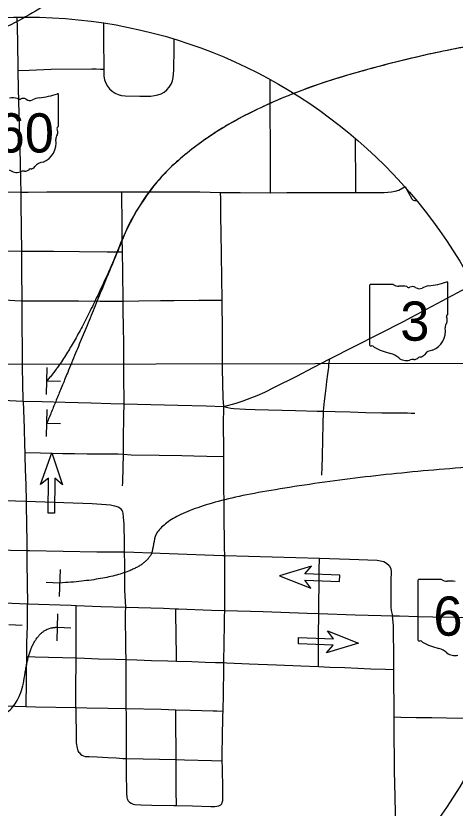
# Model space of a CAD drawing. Extents: x -15.3 to 34, y 0 to 22.
# Drawn here: x 9.062 to 11.664, y 14.569 to 19.257 of the extents above; entities that cross this region are included whole.
import ezdxf

# ---------------------------------------------------------------- set-up
doc = ezdxf.new("R2010")
doc.units = 0
for name, color, linetype in [('GM_X_City_Street', 7, 'Continuous'), ('GM_X_State_Route', 7, 'Continuous'), ('GM_X_State_Shield', 7, 'Continuous'), ('GM_X_Township', 7, 'Continuous'), ('PM_P_Cells', 7, 'Continuous'), ('SH_Text', 7, 'Continuous'), ('SN_P_Signs', 7, 'Continuous')]:
    doc.layers.add(name, color=color, linetype=linetype)

msp = doc.modelspace()

# ---------------------------------------------------------------- linework, layer by layer
at = {"layer": 'GM_X_City_Street'}
for points in [[(9.5818, 19.215), (9.5815, 19.1232), (9.5821, 18.9424)], [(9.0756, 18.9338), (9.1398, 18.9361), (9.2709, 18.9409), (9.5111, 18.9434), (9.5372, 18.943), (9.563, 18.9427), (9.5821, 18.9424), (9.5827, 18.9), (9.5872, 18.8789), (9.5941, 18.8594), (9.6038, 18.841), (9.6164, 18.8246), (9.6317, 18.8106), (9.649, 18.7994), (9.668, 18.7912), (9.6882, 18.7862), (9.7092, 18.7836), (9.7961, 18.7816), (9.8611, 18.7827), (9.8822, 18.7852), (9.9029, 18.7893), (9.9224, 18.7963), (9.9403, 18.8066), (9.9565, 18.8201), (9.9704, 18.836), (9.9815, 18.8538), (9.9888, 18.8729), (9.9935, 18.8933), (9.9971, 18.9361), (9.999, 19.0669), (9.9995, 19.1197)], [(10.5706, 18.2105), (10.5704, 18.2597), (10.5701, 18.3374), (10.5695, 18.4652), (10.5683, 18.713), (10.5675, 18.8804)], [(11.0759, 18.2114), (11.0756, 18.248), (11.073, 18.5315)], [(11.0759, 18.2114), (11.1114, 18.2113), (11.243, 18.2119), (11.2869, 18.2151), (11.3089, 18.219), (11.3306, 18.2258), (11.3682, 18.2468)], [(11.3682, 18.2468), (11.3858, 18.214), (11.4067, 18.1751), (11.4151, 18.1669), (11.4236, 18.1637), (11.434, 18.1639), (11.435, 18.1642)], [(8.6858, 18.2157), (8.8324, 18.2164), (9.0062, 18.2151), (9.0924, 18.2147)], [(9.0924, 18.2147), (9.1346, 18.2145), (9.2462, 18.2154), (9.3541, 18.2165), (9.5199, 18.2152), (9.6887, 18.2155)], [(9.6887, 18.2155), (9.6938, 18.2155), (9.8029, 18.2155), (9.8901, 18.2156), (10.151, 18.2154), (10.2745, 18.2125)], [(9.6934, 17.8601), (9.6923, 17.9454), (9.6908, 18.0561), (9.6892, 18.1749), (9.6887, 18.2155)], [(10.2745, 18.2125), (10.2817, 18.2123), (10.3908, 18.2121), (10.5706, 18.2105)], [(10.2828, 17.5755), (10.2779, 17.9781), (10.2766, 18.0654), (10.2752, 18.1522), (10.2749, 18.1738), (10.2745, 18.2125)], [(10.5706, 18.2105), (10.6674, 18.2111), (10.8493, 18.212), (11.0759, 18.2114)], [(8.6834, 17.8697), (8.714, 17.8694), (8.8594, 17.868), (8.9809, 17.8668), (9.0968, 17.8657)], [(9.0968, 17.8657), (9.2059, 17.8647), (9.2846, 17.864), (9.4379, 17.8625), (9.6024, 17.8609), (9.6529, 17.8604), (9.6934, 17.8601)], [(9.6973, 17.5698), (9.695, 17.7419), (9.6934, 17.8601)], [(8.6815, 17.5982), (8.7641, 17.5927), (9.055, 17.5722), (9.098, 17.5703), (9.0993, 17.5703)], [(9.0993, 17.5703), (9.2765, 17.57), (9.4328, 17.5699), (9.5609, 17.5697), (9.6647, 17.5696), (9.6973, 17.5698)], [(9.6973, 17.5698), (9.791, 17.571), (9.9191, 17.5726), (9.9996, 17.5736), (10.1455, 17.5754), (10.2331, 17.5754), (10.2828, 17.5755)], [(9.7023, 16.9617), (9.702, 17.1313), (9.7019, 17.1759), (9.7018, 17.2205), (9.7017, 17.325), (9.6994, 17.4116), (9.6979, 17.5193), (9.6973, 17.5698)], [(10.2928, 16.9462), (10.2889, 16.9942), (10.2866, 17.1702), (10.2863, 17.1911), (10.2852, 17.3878), (10.2828, 17.5755)], [(10.8832, 16.9175), (10.8903, 16.9762), (10.8958, 17.0217), (10.8997, 17.0542), (10.9045, 17.0936), (10.9098, 17.1378), (10.9131, 17.1654), (10.9146, 17.1773), (10.9163, 17.1915), (10.9206, 17.2273)], [(8.6759, 16.993), (8.8134, 16.9888), (8.9053, 16.9858), (8.9824, 16.9832), (9.1055, 16.9773)], [(9.6985, 16.6629), (9.6989, 16.6833), (9.7, 16.7539), (9.7022, 16.8874), (9.7023, 16.9617)], [(10.2933, 16.6491), (10.2928, 16.6945), (10.2915, 16.8385), (10.2928, 16.9462)], [(10.2928, 16.9462), (10.3163, 16.9401), (10.3355, 16.9361), (10.3521, 16.9338), (10.4212, 16.9291), (10.4787, 16.9283), (10.718, 16.922), (10.8473, 16.9186), (10.8832, 16.9175)], [(10.8745, 16.539), (10.8756, 16.5869), (10.877, 16.6485), (10.8795, 16.7549), (10.8814, 16.838), (10.8832, 16.9175)], [(10.8832, 16.9175), (10.952, 16.9155), (11.042, 16.9131), (11.1353, 16.9106), (11.2296, 16.908), (11.2729, 16.9082), (11.3815, 16.9076), (11.4033, 16.9068), (11.4249, 16.9053)], [(9.115, 16.6734), (9.2087, 16.6714), (9.339, 16.667), (9.4098, 16.6674), (9.4846, 16.6663), (9.5194, 16.6657), (9.576, 16.6662), (9.6673, 16.6646), (9.6985, 16.6629)], [(9.6939, 16.4767), (9.6958, 16.4951), (9.6973, 16.5879), (9.6984, 16.6576), (9.6985, 16.6623), (9.6985, 16.6629)], [(9.6985, 16.6629), (9.7452, 16.6605), (9.9106, 16.6569), (10.0455, 16.6546), (10.115, 16.6531), (10.1919, 16.6514), (10.2933, 16.6491)], [(10.2988, 16.0642), (10.2983, 16.1114), (10.2964, 16.3175), (10.2944, 16.5238), (10.2933, 16.6491)], [(8.6552, 16.402), (9.0599, 16.3877), (9.1238, 16.3853)], [(9.1238, 16.3853), (9.178, 16.3827), (9.2342, 16.3808), (9.514, 16.371), (9.5958, 16.3661), (9.6223, 16.3627), (9.6455, 16.3586), (9.6678, 16.3511), (9.6844, 16.3412)], [(9.7057, 16.0847), (9.7047, 16.1377), (9.7026, 16.2494), (9.6995, 16.2898), (9.6976, 16.3147), (9.6955, 16.3218), (9.6918, 16.3304), (9.6844, 16.3412)], [(8.6445, 16.1027), (9.1269, 16.0939)], [(9.1269, 16.0939), (9.1417, 16.0937), (9.5422, 16.0864), (9.7057, 16.0847)], [(9.7123, 15.7583), (9.7081, 15.8586), (9.7072, 16.0106), (9.7057, 16.0847)], [(9.7057, 16.0847), (9.7598, 16.0841), (9.9706, 16.0748), (10.2885, 16.0645), (10.2988, 16.0642)], [(10.2989, 15.7382), (10.3001, 15.9242), (10.2988, 16.0642)], [(10.2988, 16.0642), (10.8604, 16.0475)], [(10.8556, 15.7208), (10.8561, 15.804), (10.8572, 15.8692), (10.8591, 15.9787), (10.8604, 16.0475)], [(10.8604, 16.0475), (11.0386, 16.0422), (11.2023, 16.0353), (11.2208, 16.033), (11.2416, 16.0283), (11.2578, 16.0191), (11.2726, 16.0053), (11.2823, 15.9864), (11.2848, 15.9648), (11.2831, 15.9208), (11.2828, 15.7584), (11.2849, 15.7381), (11.2917, 15.7076)], [(9.126, 15.4665), (9.1271, 15.5467), (9.13, 15.6455), (9.1313, 15.7782)], [(9.4194, 15.4573), (9.4194, 15.4606), (9.4196, 15.611), (9.4198, 15.735), (9.4199, 15.7682)], [(9.7143, 15.448), (9.7135, 15.5105), (9.7127, 15.5751), (9.7116, 15.662), (9.7121, 15.7274), (9.7123, 15.7583)], [(10.0128, 15.4386), (10.0124, 15.4691), (10.0091, 15.7223), (10.0087, 15.7481)], [(10.2942, 15.4297), (10.2943, 15.4572), (10.2949, 15.523), (10.2975, 15.6769), (10.298, 15.6988), (10.2989, 15.7382)], [(10.8539, 15.4067), (10.8542, 15.46), (10.8543, 15.4897), (10.8546, 15.5407), (10.855, 15.6093), (10.8555, 15.6986), (10.8556, 15.7208)], [(11.3004, 15.3894), (11.3002, 15.4258), (11.2997, 15.5119), (11.2991, 15.5789), (11.2984, 15.65), (11.2917, 15.7076)], [(9.1233, 15.1698), (9.1237, 15.2126), (9.1243, 15.2805), (9.1251, 15.3682), (9.1259, 15.4594), (9.126, 15.4665)], [(9.126, 15.4665), (9.1759, 15.4649), (9.2543, 15.4625), (9.3388, 15.4598), (9.4194, 15.4573)], [(9.418, 15.1641), (9.4179, 15.2638), (9.4194, 15.4573)], [(9.4194, 15.4573), (9.4681, 15.4557), (9.5506, 15.4532), (9.6515, 15.45), (9.7143, 15.448)], [(9.7159, 15.1581), (9.7157, 15.1713), (9.7156, 15.201), (9.7154, 15.254), (9.715, 15.3698), (9.7143, 15.4453), (9.7143, 15.448)], [(9.7143, 15.448), (9.7792, 15.4459), (9.8651, 15.4432), (9.961, 15.4402), (10.0128, 15.4386)], [(10.0128, 15.4386), (10.1035, 15.4357), (10.1828, 15.4332), (10.244, 15.4313), (10.2942, 15.4297)], [(10.2891, 15.1434), (10.2912, 15.2457), (10.2941, 15.3918), (10.2942, 15.4297)], [(10.2942, 15.4297), (10.3122, 15.4292), (10.4435, 15.4234), (10.6056, 15.4168), (10.7498, 15.411), (10.8539, 15.4067)], [(10.8539, 15.4067), (10.9207, 15.404), (11.0101, 15.4004), (11.1632, 15.3939), (11.2508, 15.391), (11.3004, 15.3894)], [(11.3025, 15.1084), (11.3028, 15.1562), (11.3014, 15.2002), (11.3009, 15.2887), (11.3004, 15.3894)], [(8.6087, 15.1879), (8.7321, 15.1836), (8.9236, 15.1768), (9.1233, 15.1698)], [(9.1233, 15.1698), (9.1783, 15.1689), (9.418, 15.1641)], [(9.418, 15.1641), (9.4828, 15.1628), (9.6087, 15.1603), (9.7159, 15.1581)], [(9.4367, 14.8982), (9.431, 14.9088), (9.4265, 14.923), (9.4219, 14.956), (9.4203, 14.9796), (9.4181, 15.1545), (9.418, 15.1641)], [(9.7173, 14.8622), (9.7174, 14.8681), (9.7178, 14.8897), (9.7165, 14.9768), (9.7168, 14.9983), (9.7168, 15.0203), (9.7165, 15.1057), (9.7163, 15.1275), (9.7159, 15.1581)], [(9.7159, 15.1581), (9.923, 15.1539), (10.0098, 15.1511)], [(10.0108, 14.8564), (10.011, 14.8986), (10.0106, 14.943), (10.0097, 15.0289), (10.009, 15.0984), (10.0094, 15.1205), (10.0098, 15.1511)], [(10.0098, 15.1511), (10.0934, 15.1484), (10.1638, 15.1462), (10.2296, 15.1446), (10.2516, 15.1442), (10.2891, 15.1434)], [(10.2842, 14.8487), (10.2843, 14.902), (10.2859, 14.9808), (10.2886, 15.1166), (10.2891, 15.1434)], [(11.3719, 14.2621), (11.3573, 14.2741), (11.3446, 14.2901), (11.3336, 14.3081), (11.3257, 14.3273), (11.3196, 14.3479), (11.3149, 14.3685), (11.3123, 14.3898), (11.3099, 14.4332), (11.3097, 14.5427), (11.3073, 14.7179), (11.3053, 14.7837), (11.3042, 14.8711), (11.3017, 14.9808), (11.3025, 15.1084)], [(11.3025, 15.1084), (11.3427, 15.1077), (11.4322, 15.106), (11.5263, 15.1042), (11.6114, 15.1025), (11.7164, 15.1005), (11.8596, 15.0978), (11.8946, 15.0971)], [(9.4367, 14.8982), (9.4441, 14.8888), (9.453, 14.8817), (9.4622, 14.8778), (9.4726, 14.8752), (9.4963, 14.8739), (9.5425, 14.8715), (9.6069, 14.8682), (9.6565, 14.8656), (9.6946, 14.8634), (9.7173, 14.8622)], [(9.7343, 14.6047), (9.7276, 14.612), (9.7221, 14.6234), (9.7203, 14.6314), (9.7197, 14.6567), (9.7175, 14.7841), (9.7169, 14.8058), (9.7175, 14.8247), (9.7172, 14.8463), (9.7173, 14.8622)], [(9.7173, 14.8622), (10.0108, 14.8564)], [(10.0108, 14.8564), (10.0603, 14.855), (10.2215, 14.8505), (10.2842, 14.8487)], [(10.0124, 14.5846), (10.0123, 14.6036), (10.0119, 14.6532), (10.0116, 14.7095), (10.0111, 14.7823), (10.0108, 14.8332), (10.0108, 14.8564)], [(10.2754, 14.5882), (10.2813, 14.5952), (10.2846, 14.6019), (10.2874, 14.6132), (10.2883, 14.6237), (10.2882, 14.6826), (10.2852, 14.8052), (10.2842, 14.8487)], [(9.7343, 14.6047), (9.7444, 14.5973), (9.7557, 14.592), (9.767, 14.59), (9.8022, 14.5881), (9.8674, 14.5858), (9.9982, 14.5849), (10.0124, 14.5846)], [(10.0124, 14.5846), (10.1071, 14.5825), (10.216, 14.5782), (10.2409, 14.5789), (10.2517, 14.5797), (10.2636, 14.5821), (10.2754, 14.5882)]]:
    msp.add_lwpolyline(points, dxfattribs=at)
at = {"layer": 'GM_X_State_Route'}
for points in [[(9.0911, 18.2852), (9.0892, 18.3891), (9.0824, 18.6072), (9.0769, 18.8255), (9.0756, 18.9338), (9.0734, 19.1091), (9.0704, 19.2495)], [(9.0924, 18.2147), (9.0911, 18.2852)], [(9.1055, 16.9773), (9.1025, 17.0853), (9.1012, 17.1723), (9.1005, 17.2159), (9.1004, 17.3243), (9.1001, 17.3885), (9.0999, 17.4962), (9.0993, 17.5703), (9.0979, 17.7575), (9.0968, 17.8657), (9.0954, 17.9972), (9.0936, 18.1495), (9.0924, 18.2147)], [(11.4091, 17.4766), (11.7052, 17.6347), (11.7681, 17.6691)], [(9.1055, 16.9773), (9.2175, 16.9744), (9.3548, 16.9708), (9.5087, 16.9667), (9.6242, 16.9637), (9.7023, 16.9617), (9.7829, 16.9595), (10.0211, 16.9533), (10.1895, 16.9489), (10.2928, 16.9462), (10.3658, 16.965), (10.4073, 16.9788), (10.4595, 16.9983), (10.4904, 17.0098), (10.5358, 17.0303), (10.5943, 17.0591), (10.7267, 17.1243), (10.8236, 17.1758), (10.9206, 17.2273), (11.3577, 17.4492), (11.4091, 17.4766)], [(9.1055, 16.9773), (9.1105, 16.8166), (9.1135, 16.7179), (9.115, 16.6734), (9.1154, 16.6543), (9.1179, 16.5737), (9.1207, 16.4829), (9.1238, 16.3853), (9.1237, 16.3621), (9.1263, 16.1379), (9.1269, 16.0939), (9.1277, 16.0228), (9.1292, 15.8977), (9.1313, 15.7782), (9.3895, 15.7693), (9.4199, 15.7682), (9.5646, 15.763), (9.7123, 15.7583), (9.9367, 15.7512), (10.0087, 15.7481), (10.0242, 15.7474), (10.2213, 15.7405), (10.2989, 15.7382), (10.5271, 15.7315), (10.7873, 15.7234), (10.8556, 15.7208), (11.071, 15.7126), (11.2245, 15.7095), (11.2917, 15.7076), (11.334, 15.7063), (11.4434, 15.7027), (11.531, 15.7), (11.662, 15.6981), (11.9021, 15.6948)], [(8.9911, 15.7839), (9.1313, 15.7782)]]:
    msp.add_lwpolyline(points, dxfattribs=at)
at = {"layer": 'GM_X_State_Shield'}
for p, q in [((9.3143, 18.6065), (9.3143, 18.7907)), ((9.3143, 18.6065), (9.3143, 18.6065)), ((11.6205, 17.4928), (11.6205, 17.6771)), ((11.1565, 17.6623), (11.1565, 17.3101)), ((11.297, 17.6683), (11.1611, 17.6683)), ((11.6205, 17.4929), (11.6205, 17.4928)), ((11.4426, 15.9166), (11.4426, 15.5644)), ((11.5831, 15.9227), (11.4472, 15.9227))]:
    msp.add_line(p, q, dxfattribs=at)
for centre, radius, start, end in [((9.0404, 18.5842), 0.1872, 80.4867, 94.9883), ((9.0829, 18.7785), 0.015, 219.7921, 297.1024), ((9.105, 18.7378), 0.0313, 54.4667, 119.1411), ((9.1453, 18.7936), 0.0376, 233.8562, 294.8282), ((9.2118, 18.6744), 0.099, 97.3462, 120.7689), ((9.149, 19.2622), 0.4921, 275.8445, 288.9065), ((9.3092, 18.7915), 0.00517, 351.8621, 97.738), ((9.3131, 18.5929), 0.00799, 107.944, 210.337), ((9.2623, 18.5696), 0.048, 340.033, 23.6496), ((9.3088, 18.6057), 0.00553, 289.6038, 7.7341), ((9.1766, 18.5059), 0.1231, 292.3089, 8.9858), ((9.3328, 18.5293), 0.0349, 136.8065, 186.9296), ((9.2285, 18.3248), 0.0674, 94.4031, 142.5768), ((9.0676, 18.4016), 0.0706, 230.7004, 286.2918), ((9.1084, 18.2799), 0.058, 85.6951, 111.2099), ((9.1136, 18.3753), 0.0376, 268.777, 315.5493), ((9.1476, 18.3411), 0.0106, 65.7517, 132.6484), ((9.1431, 18.3896), 0.0398, 282.8732, 323.2771), ((11.4552, 18.1485), 0.4921, 275.8445, 288.9065), ((11.6154, 17.6778), 0.00517, 351.8621, 97.738), ((11.1618, 17.663), 0.00538, 98.1301, 188.1301), ((11.3293, 17.7092), 0.0521, 231.6195, 271.1119), ((11.3466, 17.4706), 0.1872, 80.4867, 94.9883), ((11.3891, 17.6649), 0.015, 219.7921, 297.1024), ((11.4112, 17.6241), 0.0313, 54.4667, 119.1411), ((11.4516, 17.68), 0.0376, 233.8562, 294.8282), ((11.518, 17.5608), 0.099, 97.3462, 120.7689), ((11.615, 17.4921), 0.00553, 289.6038, 7.7341), ((11.6193, 17.4793), 0.00799, 107.944, 210.337), ((11.5685, 17.456), 0.048, 340.033, 23.6496), ((11.4828, 17.3923), 0.1231, 292.3089, 8.9858), ((11.639, 17.4157), 0.0349, 136.8065, 186.9296), ((11.1618, 17.3093), 0.00542, 171.9584, 258.3066), ((11.1627, 17.3453), 0.0414, 267.339, 280.6039), ((11.1711, 17.2897), 0.0149, 29.7484, 93.2717), ((11.3596, 17.6062), 0.3554, 240.4129, 257.1985), ((11.2536, 17.1518), 0.1112, 47.1842, 75.836), ((11.5347, 17.2112), 0.0674, 94.4031, 142.5768), ((11.3739, 17.288), 0.0706, 230.7004, 286.2918), ((11.4146, 17.1662), 0.058, 85.6951, 111.2099), ((11.4198, 17.2616), 0.0376, 268.777, 315.5493), ((11.4538, 17.2275), 0.0106, 65.7517, 132.6484), ((11.4493, 17.2759), 0.0398, 282.8732, 323.2771), ((11.4479, 15.9173), 0.00538, 98.1301, 188.1301), ((11.6154, 15.9635), 0.0521, 231.6195, 271.1119), ((11.6327, 15.7249), 0.1872, 80.4867, 94.9883), ((11.448, 15.5636), 0.00542, 171.9584, 258.3066), ((11.4488, 15.5996), 0.0414, 267.339, 280.6039), ((11.4572, 15.5441), 0.0149, 29.7484, 93.2717), ((11.6457, 15.8605), 0.3554, 240.4129, 257.1985), ((11.5397, 15.4061), 0.1112, 47.1842, 75.836), ((11.66, 15.5423), 0.0706, 230.7004, 286.2918)]:
    msp.add_arc(centre, radius, start, end, dxfattribs=at)
at = {"layer": 'GM_X_Township'}
msp.add_line((6.2762, 17.1903), (11.9695, 17.2034), dxfattribs=at)
at = {"layer": 'PM_P_Cells'}
for p, q in [((9.2082, 16.4839), (9.2749, 16.6708)), ((9.2749, 16.6708), (9.2749, 16.6708)), ((9.2749, 16.6708), (9.3384, 16.4828)), ((9.2548, 16.521), (9.2082, 16.4839)), ((9.2531, 16.3147), (9.2548, 16.521)), ((9.2923, 16.5207), (9.2906, 16.3144)), ((9.3384, 16.4828), (9.2923, 16.5207)), ((9.2906, 16.3144), (9.2531, 16.3147)), ((9.2719, 16.3146), (9.2719, 16.3146)), ((10.8133, 16.0008), (10.6235, 15.9429)), ((10.7741, 15.9559), (10.8133, 16.0008)), ((10.6235, 15.9429), (10.6235, 15.9429)), ((10.6235, 15.9429), (10.8083, 15.8706)), ((10.9802, 15.9479), (10.7741, 15.9559)), ((10.9787, 15.9105), (10.9802, 15.9479)), ((10.8083, 15.8706), (10.7726, 15.9184)), ((10.7726, 15.9184), (10.9787, 15.9105)), ((10.9794, 15.9292), (10.9794, 15.9292)), ((10.9427, 15.5699), (10.907, 15.6177)), ((10.907, 15.6177), (11.0919, 15.5454)), ((10.7352, 15.5404), (10.7366, 15.5778)), ((10.7366, 15.5778), (10.9427, 15.5699)), ((10.9413, 15.5324), (10.7352, 15.5404)), ((10.7359, 15.5591), (10.7359, 15.5591)), ((11.0919, 15.5454), (10.902, 15.4875)), ((10.902, 15.4875), (10.9413, 15.5324)), ((11.0919, 15.5454), (11.0919, 15.5454))]:
    msp.add_line(p, q, dxfattribs=at)
at = {"layer": 'SH_Text'}
msp.add_circle((9.125, 16.25), 3, dxfattribs=at)
for points in [[(9.492, 19.6955), (9.5648, 19.4628), (8.3529, 18.8728), (8.6057, 18.3944), (8.9661, 17.4512)], [(13.3021, 19.1711), (12.2978, 19.2528), (9.9791, 18.6237), (9.4364, 17.3134), (9.2457, 17.0971)], [(13.3021, 19.1711), (12.2978, 19.2528), (9.9791, 18.6237), (9.4364, 17.3134), (9.2457, 16.8477)], [(13.3933, 16.5865), (12.7565, 16.6431), (11.2169, 16.559), (9.8779, 16.3302), (9.8779, 15.9334), (9.3211, 15.9009)], [(5.798, 11.6248), (6.3175, 11.4183), (7.5535, 14.563), (8.511, 15.0934), (9.0764, 15.0634), (9.1523, 15.6418), (9.3083, 15.6391)]]:
    msp.add_open_spline(points, degree=2, dxfattribs=at)
at = {"layer": 'SN_P_Signs'}
for p, q in [((9.2436, 17.0171), (9.2478, 17.1771)), ((9.2457, 17.0971), (9.3256, 17.095)), ((9.2436, 16.7678), (9.2478, 16.9277)), ((9.2457, 16.8477), (9.3256, 16.8456)), ((9.3239, 15.9809), (9.3184, 15.821)), ((9.3211, 15.9009), (9.2412, 15.9037)), ((9.3055, 15.5591), (9.311, 15.719)), ((9.0202, 15.6546), (9.1001, 15.6518)), ((9.3083, 15.6391), (9.3882, 15.6363))]:
    msp.add_line(p, q, dxfattribs=at)

# ---------------------------------------------------------------- texts
at = {"layer": 'GM_X_State_Shield'}
for s, height, p in [('60', 0.23203, (8.9423, 18.4485)), ('3', 0.232, (11.3385, 17.3349)), ('60', 0.23203, (11.5347, 15.5892))]:
    msp.add_text(s, height=height, dxfattribs=at).set_placement(p)

doc.saveas('drawing.dxf')
